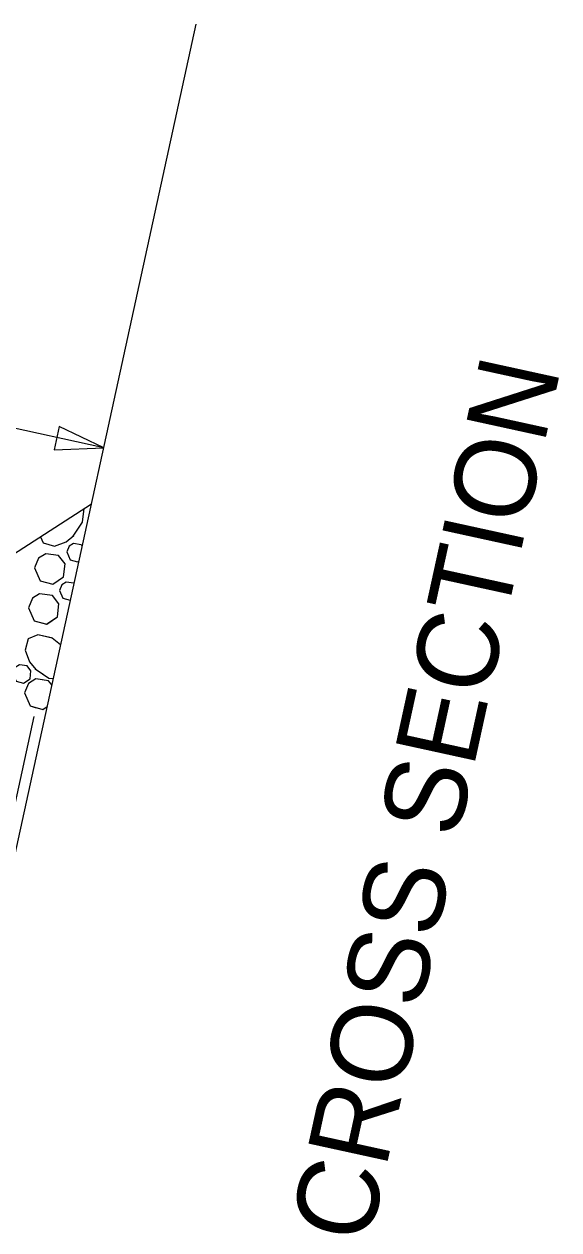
# Model space of a CAD drawing. Extents: x 2126110 to 2128246, y 1804858 to 1811658.
# Drawn here: x 2126638.8 to 2126704.7, y 1804958.2 to 1805106.9 of the extents above; entities that cross this region are included whole.
import ezdxf

# ---------------------------------------------------------------- set-up
doc = ezdxf.new("R2010")
doc.units = 0
doc.layers.add('1', color=7, linetype='Continuous')
doc.layers.add('Old_Level_1', color=7, linetype='Continuous')

msp = doc.modelspace()

# ---------------------------------------------------------------- linework, layer by layer
at = {"layer": '1'}
for p, q in [((2126635.66, 1804995.49), (2126660.01, 1805106.92)), ((2126648.6, 1805054.68), (2126634.1, 1805057.85)), ((2126599.44, 1805017.01), (2126647.08, 1805047.76)), ((2126634.52, 1804996.26), (2126640.04, 1805021.52))]:
    msp.add_line(p, q, dxfattribs=at)
msp.add_lwpolyline([(2126642.51, 1805054.42), (2126648.6, 1805054.68), (2126643.11, 1805057.31)], close=True, dxfattribs=at)
for points in [[(2126644.85, 1805043.79), (2126645.98, 1805045.48), (2126646.19, 1805047.18)], [(2126640.8, 1805043.7), (2126641.13, 1805042.93), (2126642.53, 1805042.53), (2126643.97, 1805043.08), (2126644.93, 1805043.86)], [(2126640.8, 1805043.7), (2126641.13, 1805042.93), (2126642.53, 1805042.54), (2126643.97, 1805043.08), (2126644.92, 1805043.85)], [(2126645.95, 1805042.56), (2126645.82, 1805042.72), (2126644.87, 1805042.86), (2126644.34, 1805042.52), (2126644.04, 1805041.82)], [(2126640.08, 1805039.88), (2126640.77, 1805038.27), (2126642.33, 1805037.84), (2126643.66, 1805038.74), (2126643.84, 1805040.37), (2126643.04, 1805041.38), (2126641.46, 1805041.6), (2126640.58, 1805041.05), (2126640.08, 1805039.88)], [(2126644.04, 1805041.82), (2126644.45, 1805040.85), (2126645.39, 1805040.6), (2126645.54, 1805040.7)], [(2126644.94, 1805037.97), (2126644.93, 1805037.98), (2126643.98, 1805038.11), (2126643.45, 1805037.78), (2126643.16, 1805037.08)], [(2126643.16, 1805037.08), (2126643.57, 1805036.11), (2126644.48, 1805035.86)], [(2126643.08, 1805035.38), (2126643.08, 1805035.44), (2126642.28, 1805036.45), (2126640.7, 1805036.67), (2126639.82, 1805036.12), (2126639.32, 1805034.95)], [(2126639.32, 1805034.95), (2126640.01, 1805033.33), (2126641.57, 1805032.91), (2126642.9, 1805033.81), (2126643.08, 1805035.44), (2126642.28, 1805036.45), (2126640.7, 1805036.67), (2126639.82, 1805036.12), (2126639.32, 1805034.95)], [(2126639.32, 1805034.95), (2126640.01, 1805033.33), (2126641.56, 1805032.91), (2126642.7, 1805033.68)], [(2126642.17, 1805031.22), (2126640.46, 1805031.61), (2126639.3, 1805031.11), (2126638.91, 1805029.72), (2126639.45, 1805028.27), (2126640.22, 1805027.33)], [(2126643.28, 1805030.37), (2126642.23, 1805031.2), (2126640.46, 1805031.61), (2126639.3, 1805031.11), (2126638.91, 1805029.72), (2126639.45, 1805028.27), (2126640.22, 1805027.33)], [(2126637.37, 1805026.86), (2126637.79, 1805025.89), (2126638.72, 1805025.64), (2126639.52, 1805026.18), (2126639.63, 1805027.15), (2126639.15, 1805027.76), (2126638.2, 1805027.89), (2126637.67, 1805027.56), (2126637.37, 1805026.86)], [(2126640.16, 1805027.4), (2126641.18, 1805026.72)], [(2126640.16, 1805027.4), (2126641.85, 1805026.27), (2126642.37, 1805026.21)], [(2126641.04, 1805026.05), (2126640.23, 1805026.16), (2126639.34, 1805025.61), (2126638.85, 1805024.44)], [(2126642.21, 1805025.43), (2126641.8, 1805025.94), (2126640.23, 1805026.16), (2126639.34, 1805025.61), (2126638.85, 1805024.44)], [(2126638.85, 1805024.44), (2126639.53, 1805022.83), (2126640.29, 1805022.62)], [(2126638.85, 1805024.44), (2126639.53, 1805022.83), (2126641.09, 1805022.4), (2126641.62, 1805022.76)]]:
    msp.add_lwpolyline(points, dxfattribs=at)

# ---------------------------------------------------------------- texts
at = {"layer": 'Old_Level_1'}
msp.add_text('TYPICAL CROSS SECTION', height=10, rotation=77.6737, dxfattribs=at).set_placement((2126668.64, 1804898.14))

doc.saveas('drawing.dxf')
